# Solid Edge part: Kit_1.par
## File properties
Sűrűség: 0,000 kg/m^3
Pontosság: 0,990
Author: bmolnar
Last saved by: bmolnar
Revision: 77
Username: bmolnar
Dokumentum tartalom típus: 0
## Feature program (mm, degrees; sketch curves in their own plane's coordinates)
base feature "unnamed BaseFeature 1"
sketch for "Furat_1" plane through (-18.15, -81.65, 0) normal (1, 0, 0) x-axis (0, 0, 1)
  hole centre (0, -10.65) bore radius 2.067
hole "Furat_1" nominal diameter 5 finite  ThreadDepth = 5 mm; StartChamferOffset = 0.6 mm; StartChamferAngle = 45 deg
sketch for "Furat_2" plane through (-11, -70.2, -11) normal (0, -1, 0) x-axis (0, 0, 1)
  hole centre (0, 0) bore radius 2.067
hole "Furat_2" nominal diameter 5
sketch for "unnamed Hole 1" plane through (-11, -70.2, -11) normal (0, -1, 0) x-axis (0, 0, 1)
  hole centre (22, 0) bore radius 2.067
hole "unnamed Hole 1"
sketch for "unnamed Hole 2" plane through (-11, -70.2, -11) normal (0, -1, 0) x-axis (0, 0, 1)
  hole centre (22, -22) bore radius 2.067
hole "unnamed Hole 2"
sketch for "unnamed Hole 3" plane through (-11, -70.2, -11) normal (0, -1, 0) x-axis (0, 0, 1)
  hole centre (0, -22) bore radius 2.067
hole "unnamed Hole 3"
pattern "unnamed Pattern 1" of "Furat_2", "unnamed Hole 1", "unnamed Hole 2", "unnamed Hole 3"
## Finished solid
Body 1: solid body, 258 faces, 616 edges, 372 vertices, 2 internal voids.
  Faces by surface: plane 124, cylinder 58, swept 43, cone 26, torus 7
  Edges by curve: line 361, circle 155, spline 90, curve on surface 5, intersection 4, ellipse 1
Bounding box of the edges (mm; curved faces can reach further): 36.300 x 11.800 x 36.300, from (-18.15, -75.3, -18.15) to (18.15, -63.5, 18.15).
Cylindrical faces by radius (mm): R0.2 x18, R0.4307 x1, R0.4865 x1, R2.067 x5, R3.75 x2, R4 x4, R4.1 x12, R5.24 x1, R5.45 x2, R5.55 x2, R5.7 x1, R6 x1, R6.92 x1, R7 x1, R11.25 x6
Conical faces (half-angle, radius in mm at the cone's reference point): 0.5 deg R4.5 x4, 3 deg R6.96 x1, 7 deg R6.4156 x1, 14 deg R5.12 x1, 14 deg R5.3801 x1, 17 deg R5.12 x1, 23 deg R5.7369 x1, 42.5 deg R5.1096 x1, 45 deg R2.317 x2, 45 deg R2.367 x2, 45 deg R2.667 x1, 45 deg R4.25 x2, 45 deg R5.3 x2, 45 deg R5.35 x2, 45 deg R5.85 x1, 84 deg R5.4096 x1, 85 deg R6.73 x1, 87 deg R5.1371 x1
Toroidal faces (ring radius, tube radius in mm): R3.8 r0.2 x2, R4.4 r0.4 x2, R5.6606 r0.18 x1, R6.1131 r0.26 x1, R6.72 r0.2 x1
Planar faces by outward normal: +x 5, +y 4, +z 15, -x 7, -y 16, -z 13, oblique 64
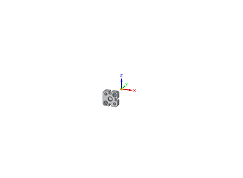
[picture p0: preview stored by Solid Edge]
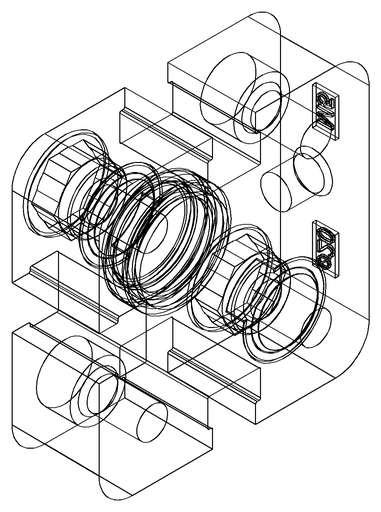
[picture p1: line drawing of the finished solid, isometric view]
